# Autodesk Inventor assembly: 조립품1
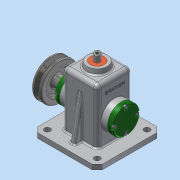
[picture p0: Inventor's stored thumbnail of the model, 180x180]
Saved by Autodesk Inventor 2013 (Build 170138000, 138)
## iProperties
Created: 2016-02
Part Number: 조립품1
Document SubType Name: Assembly
Designer: dgall
Author: dgall
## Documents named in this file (16)
- C:\Users\dgall\Desktop\460211V1012\조립품1.iam
- C:\Users\dgall\Desktop\460211V1012\V벨트풀리.ipt
- C:\Users\dgall\Desktop\460211V1012\고정핀 1.2 x 10.ipt
- C:\Users\dgall\Desktop\460211V1012\뒤커버.ipt
- C:\Users\dgall\Desktop\460211V1012\링크.ipt
- C:\Users\dgall\Desktop\460211V1012\멈춤나사 M3x8.ipt
- C:\Users\dgall\Desktop\460211V1012\베어링 12 x 32 x 10.ipt
- C:\Users\dgall\Desktop\460211V1012\본체.ipt
- C:\Users\dgall\Desktop\460211V1012\볼트 M4 x 12.ipt
- C:\Users\dgall\Desktop\460211V1012\부시.ipt
- C:\Users\dgall\Desktop\460211V1012\슬라이드.ipt
- C:\Users\dgall\Desktop\460211V1012\앞커버.ipt
- C:\Users\dgall\Desktop\460211V1012\오일실 12 25 7.ipt
- C:\Users\dgall\Desktop\460211V1012\키 4 x 4 x 10.ipt
- C:\Users\dgall\Desktop\460211V1012\편심축.ipt
- C:\Users\dgall\Desktop\460211V1012\핀 5 x 18.ipt
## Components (11 placed, 4 different names)
1. V벨트풀리:1
2. 고정핀 1.2 x 10:1
3. ISO 4762 M4 x 12:1
4. 핀 5 x 18:1 — 플러쉬:1
5. ISO 4762 M4 x 12:2
6. ISO 4762 M4 x 12:3
7. ISO 4762 M4 x 12:4
8. ISO 4762 M4 x 12:5
9. ISO 4762 M4 x 12:6
10. ISO 4762 M4 x 12:7
11. ISO 4762 M4 x 12:8
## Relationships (1: Flush 1)
- 플러쉬:1 [Flush]: 핀 5 x 18:1
